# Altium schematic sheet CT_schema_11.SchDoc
size 388 x 278 mm
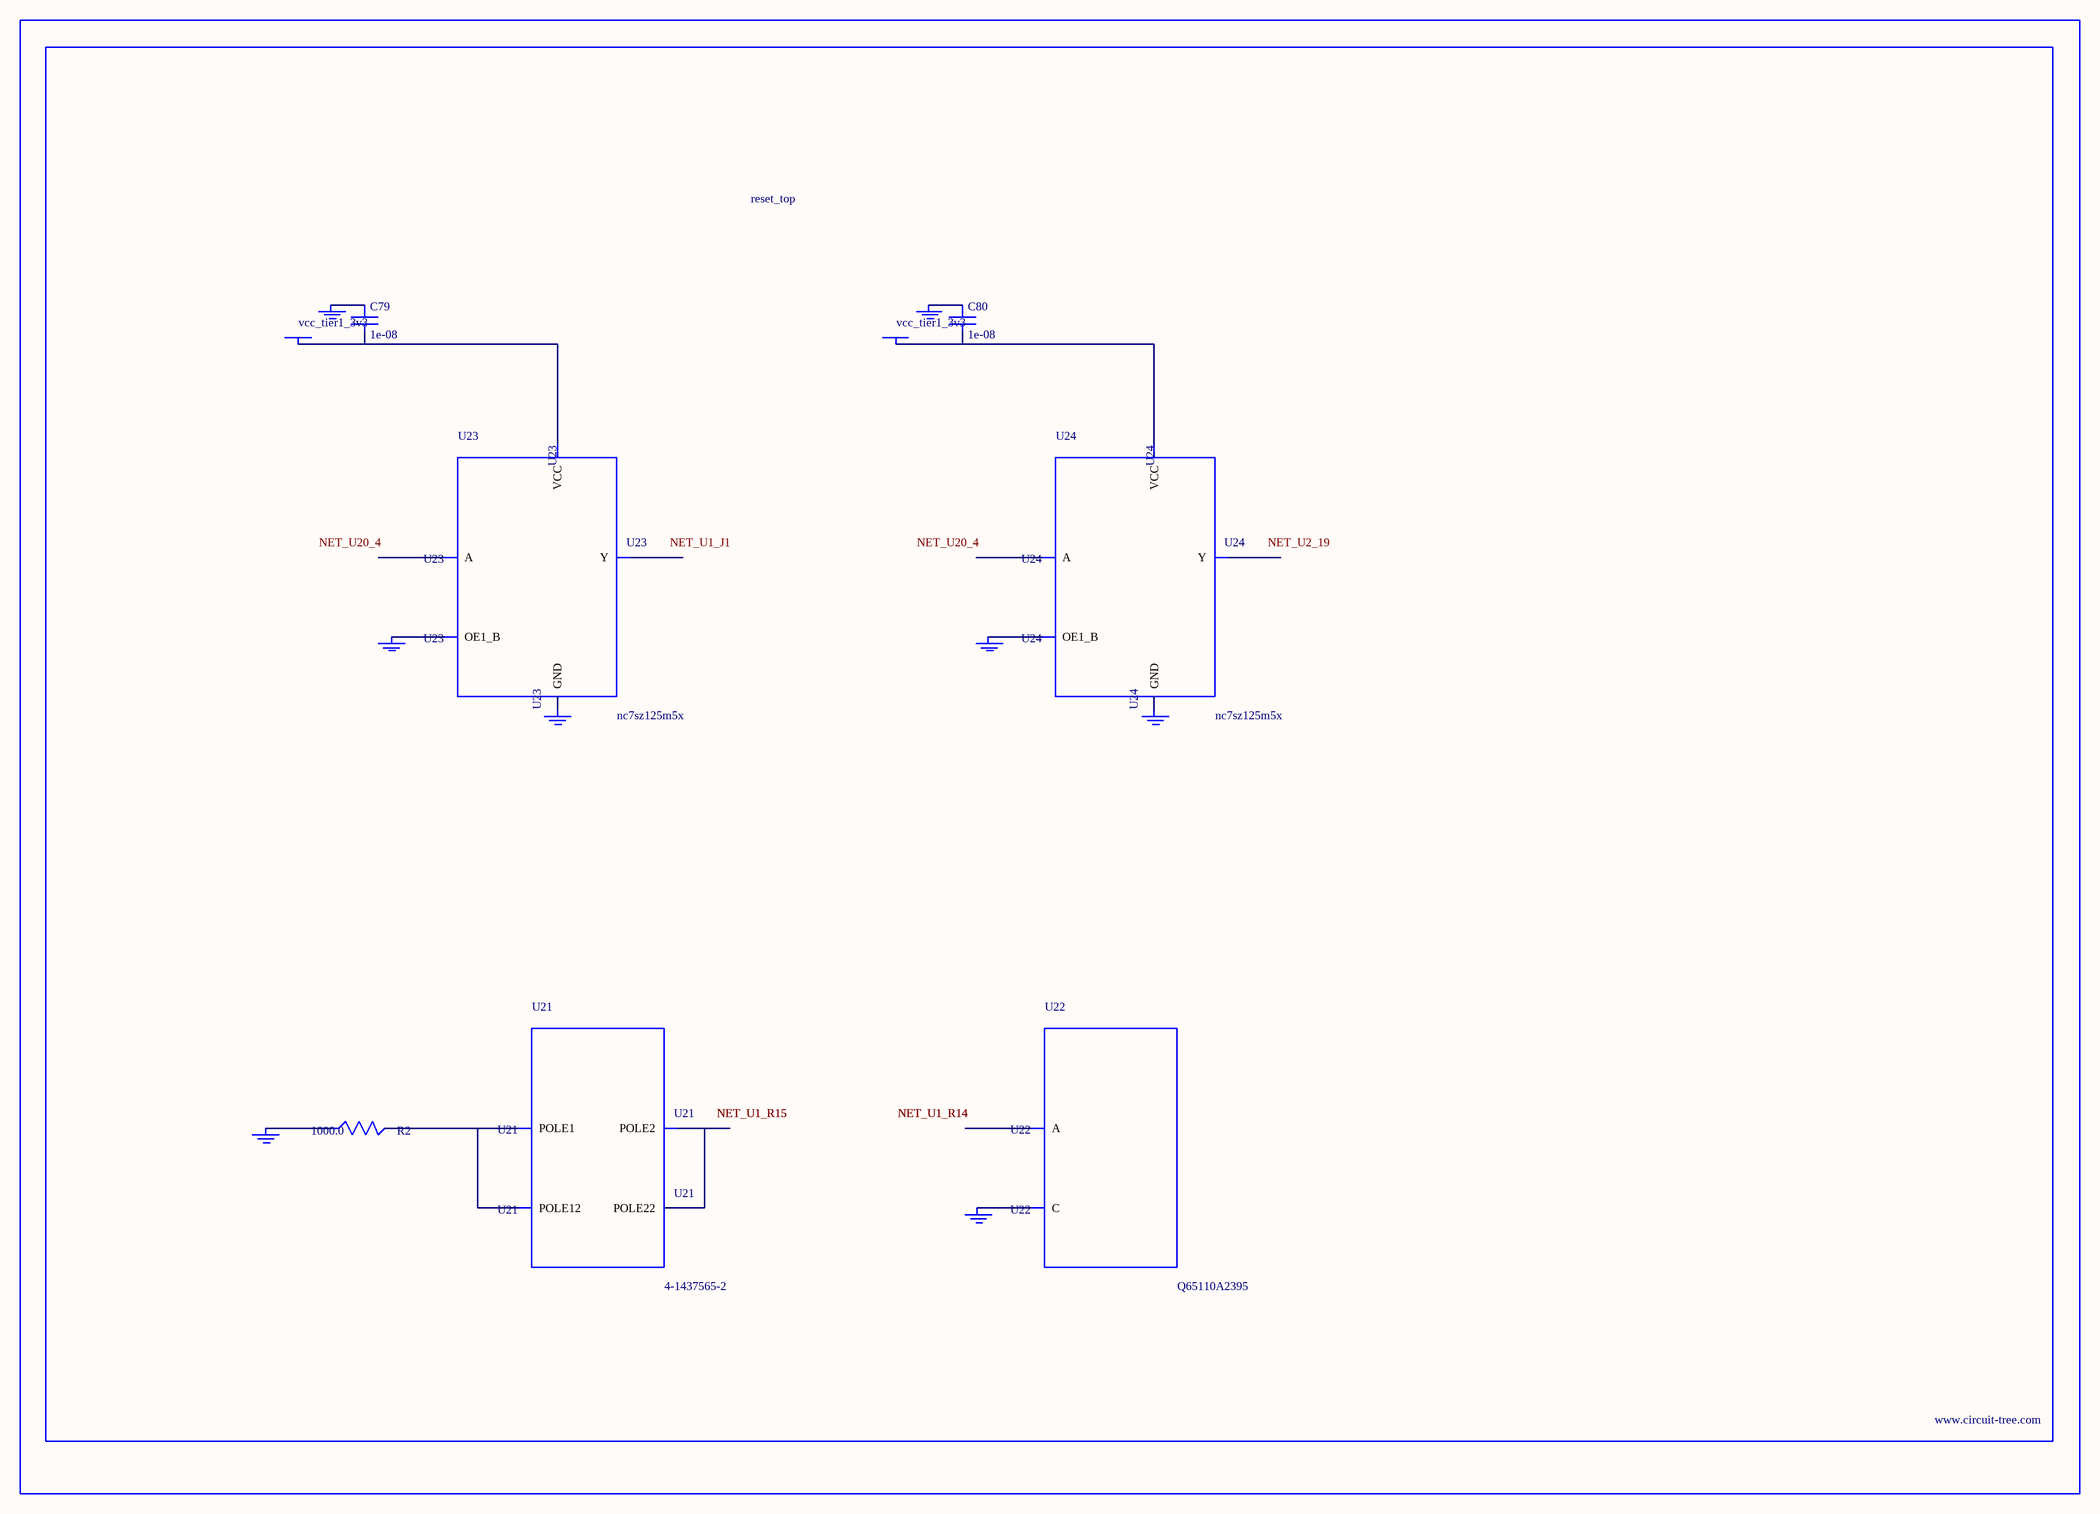
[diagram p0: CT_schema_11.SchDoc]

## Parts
BORDER10  (no value)
C79  1e-08  [C0402]
C80  1e-08  [C0402]
GND_INSTANCE_10_0  (no value)
GND_INSTANCE_10_1  (no value)
GND_INSTANCE_10_2  (no value)
GND_INSTANCE_10_3  (no value)
GND_INSTANCE_10_4  (no value)
GND_INSTANCE_10_5  (no value)
GND_INSTANCE_10_6  (no value)
GND_INSTANCE_10_7  (no value)
POWER_INSTANCE_10_0  vcc_tier1_3v3
POWER_INSTANCE_10_1  vcc_tier1_3v3
R2  1000.0  [R0603]
U21  4-1437565-2  [SW_4-1437565-2]
U22  Q65110A2395  [LGM67K-G1J2-24-Z]
U23  nc7sz125m5x  [NC7SZ125M5X]
U24  nc7sz125m5x  [NC7SZ125M5X]

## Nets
NetC79_1: C79.1 GND_INSTANCE_10_2.0(GND)
NetC79_2: C79.2 POWER_INSTANCE_10_0.0(PWR) U23.5(VCC)
NetC80_1: C80.1 GND_INSTANCE_10_5.0(GND)
NetC80_2: C80.2 POWER_INSTANCE_10_1.0(PWR) U24.5(VCC)
NetGND_INSTANCE_10_0_0: GND_INSTANCE_10_0.0(GND) R2.1
NetGND_INSTANCE_10_1_0: GND_INSTANCE_10_1.0(GND) U22.C
NetGND_INSTANCE_10_3_0: GND_INSTANCE_10_3.0(GND) U23.1(OE1_B)
NetGND_INSTANCE_10_4_0: GND_INSTANCE_10_4.0(GND) U23.3(GND)
NetGND_INSTANCE_10_6_0: GND_INSTANCE_10_6.0(GND) U24.1(OE1_B)
NetGND_INSTANCE_10_7_0: GND_INSTANCE_10_7.0(GND) U24.3(GND)
NetR2_2: R2.2 U21.1(POLE1) U21.2(POLE12)
NetU21_3: U21.3(POLE2) U21.4(POLE22)

Not connected (* = marked no-connect by the designer): U22 A; U23 2(A) 4(Y); U24 2(A) 4(Y)

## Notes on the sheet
- Labels drawn without touching a wire or pin: NET_U1_J1, NET_U2_19, NET_U20_4

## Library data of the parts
BORDER10 = BORDER_PAGE10
C79 C80 = C0402C103K3RAC
GND_INSTANCE_10_0-GND_INSTANCE_10_7 = GND
POWER_INSTANCE_10_0 POWER_INSTANCE_10_1 = PWR
R2 = RC0603JR-071KL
